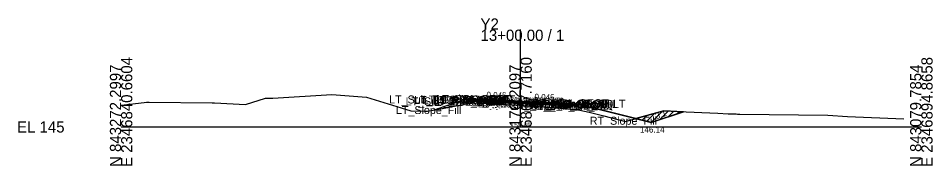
# Model space of a CAD drawing. Extents: x -26 to 2346977, y -10 to 843253.
# Drawn here: x -25.7 to 202.8, y 2490.3 to 2527.2 of the extents above; entities that cross this region are included whole.
import ezdxf

# ---------------------------------------------------------------- set-up
doc = ezdxf.new("R2010")
doc.units = 0
for name, color, linetype in [('Default', 7, 'Continuous'), ('Exist Cross Section Cell', 7, 'Continuous'), ('Exist XS Center Line Elevation Label', 7, 'Continuous'), ('Exist XS Ground Line', 7, 'Continuous'), ('Prop CMT Pvmt Course 1', 7, 'Continuous'), ('Prop CMT Pvmt Course 2', 7, 'Continuous'), ('Prop CMT Pvmt Course 3', 7, 'Continuous'), ('Prop CMT Pvmt Surface', 7, 'Continuous'), ('Prop CMT Pvmt Surface Shoulder', 7, 'Continuous'), ('Prop CMT Shld Paved Course 1', 7, 'Continuous'), ('Prop CMT Shld Paved Course 2', 7, 'Continuous'), ('Prop CMT Shld Paved Course 3', 7, 'Continuous'), ('Prop CMT Slope Grass', 7, 'Continuous'), ('Prop CMT Subgrade Earthwork', 7, 'Continuous'), ('Prop Road Sect_ Recs - UUC (Outline)', 7, 'Continuous'), ('Prop Road Sect_ Recs - UUC (pattern)', 7, 'Continuous'), ('Prop XS Earthwork Shape', 7, 'Continuous'), ('Prop XS SE Text', 7, 'Continuous'), ('Prop XS Side Slope Text', 7, 'Continuous'), ('Scratch_Level_2', 7, 'Continuous')]:
    doc.layers.add(name, color=color, linetype=linetype)

msp = doc.modelspace()

# ---------------------------------------------------------------- linework, layer by layer
at = {"layer": 'Exist Cross Section Cell'}
for p, q in [((99.83, 2500), (99.83, 2524.33)), ((0, 2500), (99.83, 2500)), ((99.83, 2500), (200, 2500))]:
    msp.add_line(p, q, dxfattribs=at)
at = {"layer": 'Exist XS Ground Line'}
msp.add_lwpolyline([(0, 2505.41), (5.76, 2506.14), (6.32, 2506.2), (7.05, 2506.2), (22.79, 2506.07), (23.31, 2506.04), (31.09, 2505.63), (36.08, 2507.22), (37.9, 2507.23), (52.67, 2508.11), (61.35, 2507.46), (70.02, 2504.8), (72.42, 2504.05), (75.85, 2503.95), (76.58, 2503.93), (82.48, 2505.05), (87.49, 2506.03), (88.29, 2506.02), (90.27, 2505.93), (91.26, 2505.88), (92.59, 2505.82), (94.32, 2505.73), (95.2, 2505.69), (96.36, 2505.63), (97.79, 2505.55), (99.43, 2505.47), (99.83, 2505.45), (100.16, 2505.43), (100.5, 2505.39), (102.94, 2505.21), (104.44, 2505.11), (105.55, 2505.02), (107.51, 2504.87), (108.13, 2504.82), (108.47, 2504.79), (109.74, 2504.7), (110.75, 2504.62), (111.57, 2504.56), (113.63, 2504.4), (114.68, 2504.18), (116.97, 2503.67), (120.67, 2502.76), (126.08, 2501.39), (130.85, 2502.7), (135.68, 2504.07), (139.2, 2503.84), (149.1, 2503.43), (151.75, 2503.28), (153.7, 2503.24), (154.08, 2503.23), (154.62, 2503.21), (176.65, 2502.97), (181.56, 2502.6), (195.66, 2502.03)], dxfattribs=at)
at = {"layer": 'Prop CMT Pvmt Course 1'}
for p, q in [((99.83, 2506.47), (88, 2507)), ((88, 2507), (88, 2506.75)), ((88, 2506.75), (99.83, 2506.22)), ((99.83, 2506.22), (99.83, 2506.47)), ((99.83, 2506.47), (112, 2505.93)), ((99.83, 2506.22), (99.83, 2506.47)), ((99.83, 2506.22), (99.83, 2506.35)), ((99.83, 2506.35), (99.83, 2506.35)), ((99.83, 2506.35), (99.83, 2506.22)), ((99.83, 2506.22), (99.83, 2506.35)), ((99.83, 2506.35), (99.83, 2506.35)), ((99.83, 2506.35), (99.83, 2506.22)), ((99.83, 2506.22), (99.83, 2506.22)), ((112, 2505.68), (99.83, 2506.22)), ((99.83, 2506.22), (99.83, 2506.22)), ((112, 2505.93), (112, 2505.68))]:
    msp.add_line(p, q, dxfattribs=at)
at = {"layer": 'Prop CMT Pvmt Course 2'}
for p, q in [((88, 2506.75), (99.83, 2506.22)), ((99.83, 2506.22), (88, 2506.75)), ((88, 2506.75), (88, 2506.75)), ((99.83, 2506.22), (99.83, 2506.22)), ((112, 2505.68), (99.83, 2506.22)), ((99.83, 2506.22), (99.83, 2506.22)), ((99.83, 2506.22), (112, 2505.68)), ((112, 2505.68), (112, 2505.68))]:
    msp.add_line(p, q, dxfattribs=at)
at = {"layer": 'Prop CMT Pvmt Course 3'}
for p, q in [((99.83, 2506.22), (88, 2506.75)), ((88, 2506.75), (88, 2506.42)), ((88, 2506.42), (99.83, 2505.89)), ((99.83, 2505.89), (99.83, 2506.22)), ((99.83, 2506.22), (112, 2505.68)), ((99.83, 2505.89), (99.83, 2506.22)), ((112, 2505.34), (99.83, 2505.89)), ((112, 2505.68), (112, 2505.34))]:
    msp.add_line(p, q, dxfattribs=at)
at = {"layer": 'Prop CMT Pvmt Surface'}
for q in [(88, 2507), (112, 2505.93)]:
    msp.add_line((99.83, 2506.47), q, dxfattribs=at)
at = {"layer": 'Prop CMT Pvmt Surface Shoulder'}
for p, q in [((88, 2507), (88, 2507)), ((112, 2505.93), (112, 2505.93))]:
    msp.add_line(p, q, dxfattribs=at)
at = {"layer": 'Prop CMT Shld Paved Course 1'}
for p, q in [((88, 2507), (87.74, 2506.74)), ((87.74, 2506.74), (88, 2506.75)), ((88, 2507), (88, 2507)), ((88, 2506.75), (88, 2507)), ((112, 2505.93), (112, 2505.93)), ((112, 2505.93), (112.25, 2505.67)), ((112, 2505.68), (112, 2505.93)), ((112.25, 2505.67), (112, 2505.68))]:
    msp.add_line(p, q, dxfattribs=at)
at = {"layer": 'Prop CMT Shld Paved Course 2'}
for p, q in [((88, 2506.75), (87.74, 2506.74)), ((87.74, 2506.74), (88, 2506.75)), ((87.74, 2506.74), (87.74, 2506.74)), ((88, 2506.75), (88, 2506.75)), ((112, 2505.68), (112.25, 2505.67)), ((112.25, 2505.67), (112, 2505.68)), ((112, 2505.68), (112, 2505.68)), ((112.25, 2505.67), (112.25, 2505.67))]:
    msp.add_line(p, q, dxfattribs=at)
at = {"layer": 'Prop CMT Shld Paved Course 3'}
for p, q in [((87.24, 2506.73), (86.9, 2506.39)), ((86.9, 2506.39), (88, 2506.42)), ((87.74, 2506.74), (87.24, 2506.73)), ((88, 2506.75), (87.74, 2506.74)), ((88, 2506.42), (88, 2506.75)), ((112, 2505.68), (112.25, 2505.67)), ((112, 2505.34), (112, 2505.68)), ((113.1, 2505.32), (112, 2505.34)), ((112.25, 2505.67), (112.75, 2505.66)), ((112.75, 2505.66), (113.1, 2505.32))]:
    msp.add_line(p, q, dxfattribs=at)
at = {"layer": 'Prop CMT Slope Grass'}
for p, q in [((86, 2506.84), (78.17, 2504.23)), ((88, 2507), (86, 2506.84)), ((112, 2505.93), (114, 2505.77)), ((114, 2505.77), (132.51, 2501.14)), ((132.51, 2501.14), (140.44, 2503.79))]:
    msp.add_line(p, q, dxfattribs=at)
at = {"layer": 'Prop CMT Subgrade Earthwork'}
for p, q in [((86.9, 2506.39), (86.43, 2506.87)), ((88, 2506.42), (86.9, 2506.39)), ((99.83, 2505.89), (88, 2506.42)), ((99.83, 2505.89), (112, 2505.34)), ((112, 2505.34), (113.1, 2505.32)), ((113.1, 2505.32), (113.57, 2505.8))]:
    msp.add_line(p, q, dxfattribs=at)
at = {"layer": 'Prop Road Sect_ Recs - UUC (Outline)'}
msp.add_lwpolyline([(128.67, 2502.1), (132.51, 2501.14), (140.53, 2503.81), (135.68, 2504.07)], close=True, dxfattribs=at)
msp.add_lwpolyline([(128.67, 2502.1), (132.51, 2501.14), (140.53, 2503.81), (135.68, 2504.07)], close=True, dxfattribs=at)
at = {"layer": 'Prop Road Sect_ Recs - UUC (pattern)'}
for p, q in [((130.24, 2501.71), (131.4, 2502.86)), ((130.24, 2501.71), (131.4, 2502.86)), ((131.37, 2501.42), (133.36, 2503.41)), ((131.37, 2501.42), (133.36, 2503.41)), ((132.5, 2501.14), (135.33, 2503.96)), ((132.5, 2501.14), (135.33, 2503.96)), ((134.62, 2501.84), (136.78, 2504.01)), ((134.62, 2501.84), (136.78, 2504.01)), ((136.74, 2502.55), (138.13, 2503.94)), ((136.74, 2502.55), (138.13, 2503.94)), ((138.86, 2503.26), (139.47, 2503.87)), ((138.86, 2503.26), (139.47, 2503.87)), ((129.11, 2501.99), (129.43, 2502.31)), ((129.11, 2501.99), (129.43, 2502.31))]:
    msp.add_line(p, q, dxfattribs=at)
at = {"layer": 'Prop XS Earthwork Shape'}
for points in [[(86, 2506.84), (78.17, 2504.23), (82.48, 2505.05), (87.49, 2506.03), (88.29, 2506.02), (90.27, 2505.93), (91.26, 2505.88), (92.59, 2505.82), (94.32, 2505.73), (95.2, 2505.69), (96.36, 2505.63), (97.79, 2505.55), (99.43, 2505.47), (99.83, 2505.45), (100.16, 2505.43), (100.5, 2505.39), (102.94, 2505.21), (104.44, 2505.11), (105.55, 2505.02), (107.51, 2504.87), (108.13, 2504.82), (108.47, 2504.79), (109.74, 2504.7), (110.75, 2504.62), (111.57, 2504.56), (113.63, 2504.4), (114.68, 2504.18), (116.97, 2503.67), (120.67, 2502.76), (126.08, 2501.39), (128.67, 2502.1), (114, 2505.77), (113.57, 2505.8), (113.1, 2505.32), (112, 2505.34), (99.83, 2505.89), (88, 2506.42), (86.9, 2506.39), (86.43, 2506.87)], [(139.2, 2503.84), (140.44, 2503.79), (132.51, 2501.14), (128.67, 2502.1), (130.85, 2502.7), (135.68, 2504.07)]]:
    msp.add_lwpolyline(points, close=True, dxfattribs=at)

# ---------------------------------------------------------------- texts
at = {"layer": 'Default'}
msp.add_text('-', height=0.0001, dxfattribs=at).set_placement((0, 2500))
at = {"layer": 'Exist Cross Section Cell'}
for s, p in [('Y2', (89.83, 2524.33)), ('13+00.00 / 1', (89.83, 2521.53)), ('EL 145', (-26, 2498.6))]:
    msp.add_text(s, height=2.8, dxfattribs=at).set_placement(p)
for s, p in [('E 2346840.6604', (2.8, 2490)), ('E 2346867.7160', (102.63, 2490)), ('E 2346894.8658', (202.8, 2490)), ('N 843272.2997', (0, 2490)), ('N 843176.2097', (99.83, 2490)), ('N 843079.7854', (200, 2490))]:
    msp.add_text(s, height=2.8, rotation=90, dxfattribs=at).set_placement(p)
at = {"layer": 'Exist XS Center Line Elevation Label'}
msp.add_text('150.45', height=1.2, dxfattribs=at).set_placement((97.33, 2499.85))
at = {"layer": 'Prop XS SE Text'}
for s, rotation, p in [('0.045', 357.4399, (91.28, 2507.32)), ('0.045', 357.4399, (103.28, 2506.83)), ('4:1', 345.9638, (120.18, 2504.76)), ('3:1', 18.4349, (133.79, 2501.94)), ('146.14', 360, (129.69, 2498.6))]:
    msp.add_text(s, height=1.5, rotation=rotation, dxfattribs=at).set_placement(p)
at = {"layer": 'Prop XS Side Slope Text'}
msp.add_text('3:1', height=1.5, rotation=18.4332, dxfattribs=at).set_placement((82.92, 2506.02))
at = {"layer": 'Scratch_Level_2'}
for s, p in [('LT_Sub_Trench_Out_DLT', (66.99, 2505.87)), ('LT_Sub_Trench_Out', (71.11, 2505.39)), ('LT_PS3_Shelf_Out', (73.23, 2505.73)), ('LT_GS_OS_CTL', (75.37, 2505.84)), ('LT_PS3_OEOP', (77.98, 2505.74)), ('LT_PS2_OEOP', (77.98, 2505.74)), ('LT_Sub_OEOT', (78.08, 2505.42)), ('LT_PV3_OEOT', (78.17, 2505.75)), ('LT_PV2_OEOT', (78.17, 2505.75)), ('LT_PV1_OEOT', (78.74, 2506)), ('LT_PS1_OEOP', (78.8, 2506)), ('RT_PV2_OEEOP', (89.09, 2505.22)), ('RT_PV3_OEEOP', (89.09, 2505.22)), ('LT_PV2_OEEOP', (89.13, 2505.22)), ('LT_PV3_OEEOP', (89.13, 2505.22)), ('RT_PV1_OEEOP', (89.65, 2505.35)), ('LT_PV1_OEEOP', (89.7, 2505.35)), ('RT_PV2_IEEOP', (89.73, 2505.22)), ('LT_PV2_IEEOP', (89.78, 2505.22)), ('RT_PV1_IEEOP', (90.3, 2505.35)), ('LT_PV1_IEEOP', (90.35, 2505.35)), ('PV2_PGL', (93.73, 2505.22)), ('PV1_PGL', (94.3, 2505.47)), ('LT_Slope_Fill', (68.69, 2503.23)), ('RT_Sub_OEEOP', (88.99, 2504.89)), ('LT_Sub_OEEOP', (89.04, 2504.89)), ('RT_Sub_Trench_Out_DLT', (94.09, 2504.8)), ('RT_Sub_Trench_Out', (97.25, 2504.32)), ('RT_PS3_Shelf_Out', (98.69, 2504.66)), ('RT_Sub_OEOT', (102.03, 2504.34)), ('RT_PV3_OEOT', (102.13, 2504.68)), ('RT_PV2_OEOT', (102.13, 2504.68)), ('RT_PS3_OEOP', (102.44, 2504.67)), ('RT_PS2_OEOP', (102.44, 2504.67)), ('RT_PV1_OEOT', (102.69, 2504.93)), ('RT_PS1_OEOP', (102.76, 2504.93)), ('RT_GS_OS_CTL', (103.32, 2504.77)), ('RT_Slope_Fill', (117.14, 2500.55))]:
    msp.add_text(s, height=2, dxfattribs=at).set_placement(p)

doc.saveas('drawing.dxf')
